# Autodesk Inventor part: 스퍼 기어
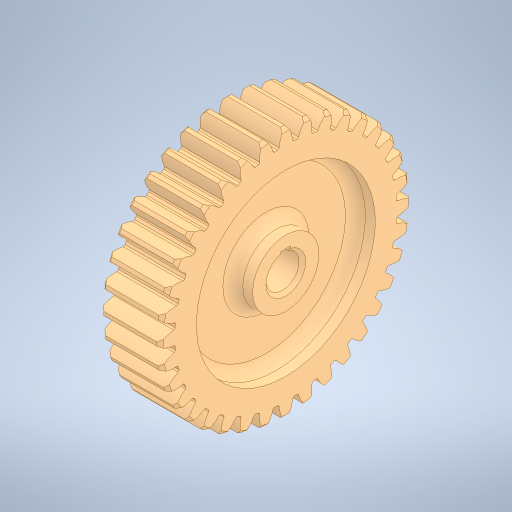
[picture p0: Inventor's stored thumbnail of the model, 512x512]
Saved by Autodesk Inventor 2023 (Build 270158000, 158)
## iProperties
Created: 2025-10
Part Number: 스퍼 기어
Material: 강철, 합금
Document SubType Name: Modeling
Designer: home
Density: 7.73 g/cm^3
Appearance: 기본값
Author: jhkim
Sending System: Autodesk Inventor 2026
Preprocessor: ST-DEVELOPER v20.1
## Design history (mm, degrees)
sketch "스케치1"
  geometry: 1 further point
  constraints: 1 other
feature "솔리드1"
node "솔리드2"
